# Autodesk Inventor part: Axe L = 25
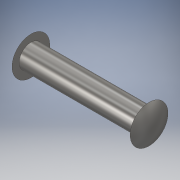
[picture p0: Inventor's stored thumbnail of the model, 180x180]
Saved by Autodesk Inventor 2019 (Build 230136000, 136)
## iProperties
Created: 2018-06
Part Number: Axe L = 25
Material: Acier inoxydable
Document SubType Name: Modeling
Designer: Fabian Perrée
Density: 8 g/cm^3
Appearance: Semi-poli
Author: Fabian Perrée
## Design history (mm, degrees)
sketch "Esquisse1"
  geometry: L1 (-12.5, 0)-(12.5, 0); L2 (12.5, 2.5)-(-12.5, 2.5); L3 (12.5, 2.5)-(12.5, 4); L4 (12.5, 0)-(13.572, 0); L5 (0, 2.5)-(0, 0); L6 (-12.5, 2.5)-(-12.5, 4); L7 (-13.572, 0)-(-12.5, 0); A1 r 8 centre (5.572, 0) between (13.572, 0) and (12.5, 4); A2 r 8 centre (-5.572, 0) between (-12.5, 4) and (-13.572, 0); 1 further point
  constraints: 14 end point, 4 horizontal, 4 point on circle, 3 symmetric about line, 2 centre point, 2 midpoint, 2 point on line, 1 coincident, 1 perpendicular, 1 vertical, 1 other
  dimensions: "d0" = 25 distance of L1.start L1.end; "d1" = 5 diameter of L2 L1; "d2" = 8 diameter of L3.end L1; "d3" = 16 diameter of A1
revolve "Révolution1" sketch "Esquisse1" stored, may be unused: angle "d4" = 90 deg
node "Solide1"
